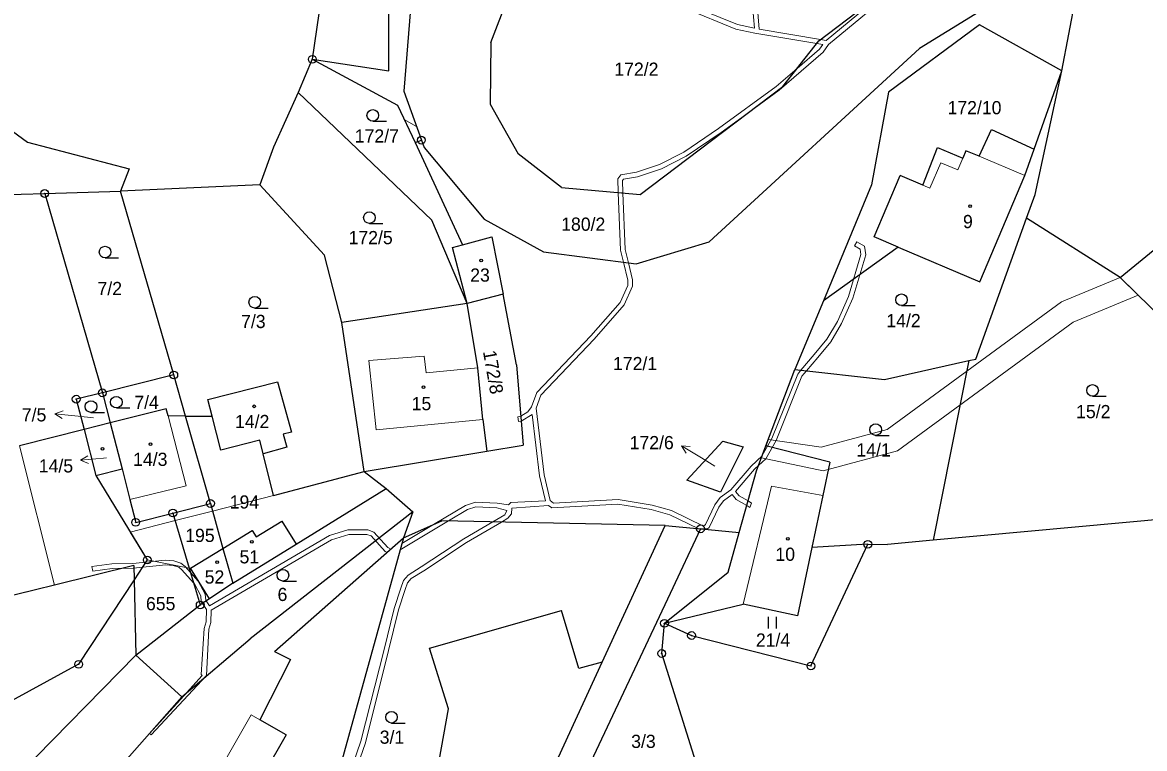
# Model space of a CAD drawing. Extents: x -653193 to -651624, y -1092017 to -1090260.
# Drawn here: x -652971.4 to -652826.7, y -1091343.3 to -1091249.7 of the extents above; entities that cross this region are included whole.
import ezdxf
from ezdxf.enums import TextEntityAlignment as Align

# ---------------------------------------------------------------- set-up
doc = ezdxf.new("R2010")
doc.units = 0
doc.header["$LTSCALE"] = 0.68
for name, color, linetype, lineweight in [('1', 7, 'Continuous', 25), ('13', 7, 'Continuous', 13), ('3', 7, 'Continuous', 25), ('4', 7, 'Continuous', 13), ('5', 7, 'Continuous', 25), ('7', 7, 'Continuous', 13), ('8', 7, 'Continuous', 25)]:
    doc.layers.add(name, color=color, linetype=linetype, lineweight=lineweight)
doc.layers.add('2', color=7, linetype='Continuous')

msp = doc.modelspace()

# ---------------------------------------------------------------- linework, layer by layer
at = {"layer": '1'}
for p, q in [((-652868.72, -1091252.07), (-652827.4, -1091220.4)), ((-652931.22, -1091234.98), (-652934.04, -1091254.46)), ((-652924.16, -1091255.94), (-652924.17, -1091237.24)), ((-652834.31, -1091239.8), (-652855.74, -1091253.08)), ((-652837.4, -1091255.94), (-652834.31, -1091239.8)), ((-652911.02, -1091252.3), (-652906.87, -1091241.53)), ((-652921.38, -1091247.95), (-652922.24, -1091258.57)), ((-652848.02, -1091250), (-652859.77, -1091258.7)), ((-652837.4, -1091255.94), (-652848.02, -1091250)), ((-652911.02, -1091252.3), (-652911.1, -1091260.26)), ((-652873.4, -1091257.98), (-652868.72, -1091252.07)), ((-652882.87, -1091278.01), (-652855.74, -1091253.08)), ((-652934.04, -1091254.46), (-652935.88, -1091258.76)), ((-652934.04, -1091254.46), (-652924.16, -1091255.94)), ((-652934.04, -1091254.46), (-652923.04, -1091260.36)), ((-652840.98, -1091266.06), (-652837.4, -1091255.94)), ((-652840.87, -1091271.87), (-652837.4, -1091255.94)), ((-652980.24, -1091258.22), (-652970.74, -1091265.15)), ((-652891.79, -1091271.87), (-652873.4, -1091257.98)), ((-652935.88, -1091258.76), (-652939.03, -1091265.77)), ((-652935.88, -1091258.76), (-652918.63, -1091275.21)), ((-652922.24, -1091258.57), (-652919.98, -1091264.88)), ((-652859.77, -1091258.7), (-652861.96, -1091270.63)), ((-652923.04, -1091260.36), (-652920.79, -1091265.2)), ((-652911.1, -1091260.26), (-652907.48, -1091266.64)), ((-652848.08, -1091266.96), (-652846.48, -1091263.49)), ((-652846.48, -1091263.49), (-652840.98, -1091266.06)), ((-652970.74, -1091265.15), (-652957.64, -1091268.57)), ((-652920.79, -1091265.2), (-652919.98, -1091264.88)), ((-652920.79, -1091265.2), (-652914.69, -1091278.37)), ((-652919.98, -1091264.88), (-652919.64, -1091265.84)), ((-652939.03, -1091265.77), (-652940.82, -1091270.66)), ((-652919.64, -1091265.84), (-652911.87, -1091275.05)), ((-652901.92, -1091270.97), (-652907.48, -1091266.64)), ((-652855.35, -1091270.69), (-652853.45, -1091265.85)), ((-652853.45, -1091265.85), (-652850.19, -1091267.2)), ((-652849.78, -1091266.24), (-652850.19, -1091267.2)), ((-652848.08, -1091266.96), (-652849.78, -1091266.24)), ((-652842.19, -1091269.46), (-652840.98, -1091266.06)), ((-652957.64, -1091268.57), (-652958.79, -1091271.46)), ((-652861.6, -1091277.36), (-652858.26, -1091269.45)), ((-652855.35, -1091270.69), (-652858.26, -1091269.45)), ((-652847.98, -1091283.13), (-652842.19, -1091269.46)), ((-652940.82, -1091270.66), (-652958.79, -1091271.46)), ((-652940.82, -1091270.66), (-652932.49, -1091279.7)), ((-652901.92, -1091270.97), (-652891.79, -1091271.87)), ((-652861.96, -1091270.63), (-652868.15, -1091285.58)), ((-652975.2, -1091271.97), (-652968.54, -1091271.76)), ((-652968.54, -1091271.76), (-652958.79, -1091271.46)), ((-652968.54, -1091271.76), (-652961.1, -1091297.46)), ((-652951.9, -1091295.15), (-652958.79, -1091271.46)), ((-652841.98, -1091274.95), (-652840.87, -1091271.87)), ((-652914.09, -1091285.93), (-652918.63, -1091275.21)), ((-652911.87, -1091275.05), (-652904.23, -1091279.27)), ((-652848.49, -1091293.1), (-652841.98, -1091274.95)), ((-652829.87, -1091282.59), (-652841.98, -1091274.95)), ((-652915.97, -1091278.71), (-652914.69, -1091278.37)), ((-652914.69, -1091278.37), (-652910.9, -1091277.36)), ((-652910.9, -1091277.36), (-652909.43, -1091284.72)), ((-652892.28, -1091280.84), (-652882.87, -1091278.01)), ((-652858.49, -1091278.67), (-652861.6, -1091277.36)), ((-652930.22, -1091288.41), (-652932.49, -1091279.7)), ((-652914.09, -1091285.93), (-652915.97, -1091278.71)), ((-652904.23, -1091279.27), (-652892.28, -1091280.84)), ((-652858.49, -1091278.67), (-652868.15, -1091285.58)), ((-652858.49, -1091278.67), (-652847.98, -1091283.13)), ((-652909.43, -1091284.72), (-652914.09, -1091285.93)), ((-652907.72, -1091293.86), (-652909.43, -1091284.72)), ((-652868.15, -1091285.58), (-652871.82, -1091294.46)), ((-652914.09, -1091285.93), (-652930.22, -1091288.41)), ((-652912.71, -1091294.23), (-652914.09, -1091285.93)), ((-652927.34, -1091307.6), (-652930.22, -1091288.41)), ((-652912.05, -1091300.89), (-652912.71, -1091294.23)), ((-652907.72, -1091293.86), (-652906.85, -1091304.2)), ((-652875.56, -1091304.31), (-652871.82, -1091294.46)), ((-652871.82, -1091294.46), (-652860.27, -1091295.72)), ((-652860.27, -1091295.72), (-652849.42, -1091293.31)), ((-652849.42, -1091293.31), (-652854.02, -1091316.45)), ((-652849.42, -1091293.31), (-652848.49, -1091293.1)), ((-652951.9, -1091295.15), (-652961.1, -1091297.46)), ((-652950.37, -1091300.46), (-652951.9, -1091295.15)), ((-652947.52, -1091298.33), (-652938.51, -1091296.02)), ((-652938.51, -1091296.02), (-652936.72, -1091302.52)), ((-652961.1, -1091297.46), (-652964.48, -1091298.27)), ((-652964.48, -1091298.27), (-652963.46, -1091302.17)), ((-652961.1, -1091297.46), (-652960.11, -1091301.32)), ((-652946.95, -1091300.48), (-652947.52, -1091298.33)), ((-652952.87, -1091299.53), (-652960.11, -1091301.32)), ((-652952.64, -1091300.44), (-652952.87, -1091299.53)), ((-652960.11, -1091301.32), (-652963.46, -1091302.17)), ((-652960.11, -1091301.32), (-652958.57, -1091307.24)), ((-652950.37, -1091300.46), (-652952.64, -1091300.44)), ((-652950.37, -1091300.46), (-652946.95, -1091300.48)), ((-652947.17, -1091311.72), (-652950.37, -1091300.46)), ((-652945.83, -1091304.83), (-652946.95, -1091300.48)), ((-652912.05, -1091300.89), (-652911.54, -1091304.98)), ((-652963.46, -1091302.17), (-652971.81, -1091304.28)), ((-652963.46, -1091302.17), (-652961.97, -1091308.11)), ((-652936.72, -1091302.52), (-652937.79, -1091302.78)), ((-652937.79, -1091302.78), (-652937.32, -1091304.47)), ((-652940.81, -1091303.56), (-652945.83, -1091304.83)), ((-652940.38, -1091305.3), (-652940.81, -1091303.56)), ((-652937.32, -1091304.47), (-652940.38, -1091305.3)), ((-652911.54, -1091304.98), (-652906.85, -1091304.2)), ((-652885.76, -1091308.73), (-652881.13, -1091303.69)), ((-652878.5, -1091304.43), (-652881.43, -1091310.26)), ((-652881.13, -1091303.69), (-652878.5, -1091304.43)), ((-652876.78, -1091307.52), (-652875.56, -1091304.31)), ((-652867.31, -1091306.39), (-652875.56, -1091304.31)), ((-652939.05, -1091310.69), (-652940.38, -1091305.3)), ((-652927.34, -1091307.6), (-652911.54, -1091304.98)), ((-652961.97, -1091308.11), (-652958.57, -1091307.24)), ((-652958.57, -1091307.24), (-652957.56, -1091311.21)), ((-652879, -1091315.45), (-652876.78, -1091307.52)), ((-652867.31, -1091306.39), (-652868.21, -1091310.68)), ((-652961.97, -1091308.11), (-652955.32, -1091319)), ((-652939.05, -1091310.69), (-652927.34, -1091307.6)), ((-652927.34, -1091307.6), (-652924.54, -1091309.8)), ((-652881.43, -1091310.26), (-652885.76, -1091308.73)), ((-652936.13, -1091316.95), (-652924.54, -1091309.8)), ((-652924.54, -1091309.8), (-652921.09, -1091312.8)), ((-652957.56, -1091311.21), (-652956.81, -1091314.16)), ((-652952.02, -1091312.95), (-652947.17, -1091311.72)), ((-652947.17, -1091311.72), (-652945.56, -1091317.51)), ((-652800.34, -1091311.51), (-652854.02, -1091316.45)), ((-652956.81, -1091314.16), (-652952.02, -1091312.95)), ((-652952.02, -1091312.95), (-652949.91, -1091320.04)), ((-652921.09, -1091312.8), (-652942.07, -1091329.19)), ((-652921.09, -1091312.8), (-652922.28, -1091316.16)), ((-652941.28, -1091316.03), (-652937.97, -1091314)), ((-652937.97, -1091314), (-652936.13, -1091316.95)), ((-652922.28, -1091316.16), (-652917.35, -1091313.95)), ((-652888.57, -1091314.54), (-652917.35, -1091313.95)), ((-652896.68, -1091332.18), (-652888.57, -1091314.54)), ((-652888.57, -1091314.54), (-652883.99, -1091314.99)), ((-652945.56, -1091317.51), (-652941.81, -1091315.21)), ((-652941.81, -1091315.21), (-652941.28, -1091316.03)), ((-652938.9, -1091330.8), (-652922.28, -1091316.16)), ((-652922.28, -1091316.16), (-652931.8, -1091350.57)), ((-652883.99, -1091314.99), (-652887.91, -1091323.32)), ((-652883.99, -1091314.99), (-652882.99, -1091315.06)), ((-652882.99, -1091315.06), (-652879, -1091315.45)), ((-652880.44, -1091320.59), (-652879, -1091315.45)), ((-652949.74, -1091320.07), (-652945.56, -1091317.51)), ((-652945.56, -1091317.51), (-652944.3, -1091321.99)), ((-652944.3, -1091321.99), (-652936.13, -1091316.95)), ((-652869.76, -1091332.67), (-652862.42, -1091316.98)), ((-652862.42, -1091316.98), (-652869.63, -1091317.4)), ((-652862.42, -1091316.98), (-652859.89, -1091316.99)), ((-652854.02, -1091316.45), (-652859.89, -1091316.99)), ((-652955.32, -1091319), (-652957, -1091321.56)), ((-652957.04, -1091319.7), (-652967.29, -1091322.23)), ((-652957.04, -1091319.7), (-652957, -1091321.56)), ((-652949.91, -1091320.04), (-652948.49, -1091324.8)), ((-652947.29, -1091324), (-652949.74, -1091320.07)), ((-652957, -1091321.56), (-652964.17, -1091332.45)), ((-652957, -1091321.56), (-652956.81, -1091331.27)), ((-652944.3, -1091321.99), (-652947.29, -1091324)), ((-652888.64, -1091327.17), (-652880.44, -1091320.59)), ((-652967.29, -1091322.23), (-652976.34, -1091324.46)), ((-652887.91, -1091323.32), (-652903.57, -1091356.54)), ((-652956.81, -1091331.27), (-652948.49, -1091324.8)), ((-652947.29, -1091324), (-652948.49, -1091324.8)), ((-652888.64, -1091327.17), (-652878.5, -1091324.71)), ((-652871.49, -1091326.22), (-652878.5, -1091324.71)), ((-652918.95, -1091330.37), (-652901.9, -1091325.5)), ((-652899.69, -1091333), (-652901.9, -1091325.5)), ((-652888.99, -1091331.06), (-652888.64, -1091327.17)), ((-652950.87, -1091336.63), (-652942.07, -1091329.19)), ((-652916.48, -1091338.19), (-652918.95, -1091330.37)), ((-652956.81, -1091331.27), (-652971.83, -1091346.61)), ((-652950.87, -1091336.63), (-652956.81, -1091331.27)), ((-652936.87, -1091331.83), (-652940.81, -1091339.6)), ((-652938.9, -1091330.8), (-652936.87, -1091331.83)), ((-652884.37, -1091345.73), (-652888.99, -1091331.06)), ((-652964.17, -1091332.45), (-652980.42, -1091341.26)), ((-652907.57, -1091355.84), (-652896.68, -1091332.18)), ((-652896.68, -1091332.18), (-652899.69, -1091333)), ((-652919.74, -1091356.26), (-652916.48, -1091338.19)), ((-652937.42, -1091341.55), (-652940.81, -1091339.6)), ((-652937.42, -1091341.55), (-652942.81, -1091350.95))]:
    msp.add_line(p, q, dxfattribs=at)
for points in [[(-652800.34, -1091311.51), (-652829.87, -1091282.59), (-652807.65, -1091264.38)], [(-652868.21, -1091310.68), (-652869.63, -1091317.4), (-652871.49, -1091326.22)], [(-652888.64, -1091327.17), (-652885.15, -1091328.74), (-652869.76, -1091332.67)]]:
    msp.add_lwpolyline(points, dxfattribs=at)
at = {"layer": '13'}
for points in [[(-652858.9, -1091244.63), (-652867.79, -1091252.03), (-652868.51, -1091251.91), (-652868.72, -1091252.07), (-652869.01, -1091252.44), (-652868.23, -1091252.57), (-652868.64, -1091253.14), (-652871.55, -1091255.65), (-652873.4, -1091257.98), (-652877.74, -1091261.26), (-652873.86, -1091258.44), (-652868.2, -1091253.54), (-652867.48, -1091252.56), (-652858.42, -1091245.02)], [(-652885.94, -1091247.91), (-652879.42, -1091250.56), (-652876.98, -1091251.08), (-652869.01, -1091252.44), (-652868.72, -1091252.07), (-652868.51, -1091251.91), (-652876.42, -1091250.57), (-652876.69, -1091247.4)], [(-652877.29, -1091247.54), (-652877.04, -1091250.46), (-652879.24, -1091249.98), (-652885.7, -1091247.37)], [(-652930.22, -1091351.36), (-652927.2, -1091342.56), (-652924.21, -1091330.69), (-652922.91, -1091325.41), (-652922.07, -1091322.82), (-652921.76, -1091321.96), (-652921.29, -1091321.41), (-652919.68, -1091320.39), (-652914.17, -1091316.76), (-652909.64, -1091314.11), (-652910.78, -1091314.08), (-652914.49, -1091316.26), (-652920, -1091319.89), (-652921.69, -1091320.95), (-652922.28, -1091321.66), (-652922.63, -1091322.62), (-652923.49, -1091325.25), (-652924.79, -1091330.55), (-652927.78, -1091342.38), (-652930.82, -1091351.26)]]:
    msp.add_lwpolyline(points, dxfattribs=at)
for points in [[(-652877.74, -1091261.26), (-652873.4, -1091257.98), (-652871.55, -1091255.65), (-652874.24, -1091257.96), (-652881.69, -1091263.38), (-652886.16, -1091266.42), (-652889.28, -1091268.04), (-652892.24, -1091269.02), (-652894.28, -1091269.37), (-652894.66, -1091269.87), (-652894.59, -1091271.62), (-652893.99, -1091271.67), (-652894.06, -1091270.07), (-652893.94, -1091269.93), (-652892.1, -1091269.6), (-652889.04, -1091268.6), (-652885.86, -1091266.94), (-652881.35, -1091263.88)], [(-652920.79, -1091265.2), (-652919.98, -1091264.88), (-652920.61, -1091263.13), (-652922.18, -1091262.21)], [(-652894.59, -1091271.62), (-652894.29, -1091279.05), (-652893.92, -1091280.62), (-652893.28, -1091280.71), (-652893.69, -1091278.97), (-652893.99, -1091271.67)], [(-652864.37, -1091285.24), (-652862.69, -1091279.68), (-652862.84, -1091278.55), (-652863.83, -1091277.99), (-652864.13, -1091278.51), (-652863.4, -1091278.93), (-652863.31, -1091279.64), (-652864.93, -1091285.04), (-652866.35, -1091288.25), (-652867.69, -1091290.55), (-652869.32, -1091292.53), (-652871.04, -1091294.54), (-652870.32, -1091294.62), (-652868.86, -1091292.91), (-652867.19, -1091290.89), (-652865.81, -1091288.53)], [(-652892.77, -1091283.72), (-652892.77, -1091282.87), (-652893.28, -1091280.71), (-652893.92, -1091280.62), (-652893.37, -1091282.93), (-652893.37, -1091283.6), (-652894.36, -1091285.81), (-652898.14, -1091290.12), (-652905.1, -1091297.42), (-652905.77, -1091299.25), (-652906.27, -1091299.9), (-652907.16, -1091300.47), (-652907.12, -1091301.1), (-652905.7, -1091300.26), (-652904.76, -1091308.14), (-652903.96, -1091311.4), (-652908.46, -1091311.61), (-652908.75, -1091311.89), (-652910.21, -1091311.68), (-652913.02, -1091311.54), (-652914.3, -1091311.96), (-652918.4, -1091314.42), (-652917.35, -1091313.95), (-652916.48, -1091313.97), (-652914.04, -1091312.5), (-652912.94, -1091312.14), (-652910.27, -1091312.28), (-652908.96, -1091312.61), (-652909.22, -1091313.17), (-652910.78, -1091314.08), (-652909.64, -1091314.11), (-652908.82, -1091313.63), (-652908.37, -1091313.04), (-652908.3, -1091312.33), (-652903.58, -1091311.98), (-652903.16, -1091312.28), (-652894.67, -1091311.81), (-652890.36, -1091312.51), (-652887.95, -1091313.18), (-652884.29, -1091314.96), (-652883.99, -1091314.99), (-652883.1, -1091314.99), (-652882.88, -1091314.8), (-652881.61, -1091312.2), (-652881.04, -1091311.36), (-652879.92, -1091310.57), (-652879.4, -1091311.19), (-652878.03, -1091312), (-652877.87, -1091311.4), (-652879, -1091310.73), (-652879.48, -1091310.17), (-652877.04, -1091307.31), (-652876.52, -1091306.83), (-652876.03, -1091305.54), (-652876.05, -1091305.58), (-652877.48, -1091306.89), (-652880.07, -1091309.95), (-652881.48, -1091310.94), (-652882.13, -1091311.9), (-652883.36, -1091314.42), (-652883.6, -1091314.63), (-652887.73, -1091312.62), (-652890.24, -1091311.93), (-652894.63, -1091311.21), (-652902.96, -1091311.66), (-652903.36, -1091311.33), (-652904.16, -1091308.04), (-652905.19, -1091299.44), (-652904.58, -1091297.74), (-652897.7, -1091290.52), (-652893.84, -1091286.13)], [(-652835.96, -1091288.35), (-652827.56, -1091284.86), (-652829.87, -1091282.59), (-652837.45, -1091285.72), (-652859.92, -1091302.2), (-652868.42, -1091304.47), (-652875.24, -1091303.47), (-652876.14, -1091305.84), (-652868.2, -1091307.52), (-652858.6, -1091304.95)], [(-652870.91, -1091295.31), (-652870.32, -1091294.62), (-652871.04, -1091294.54), (-652871.46, -1091295.03), (-652874.8, -1091303.35), (-652876.03, -1091305.54), (-652876.52, -1091306.83), (-652875.57, -1091305.96), (-652874.26, -1091303.61)], [(-652907.12, -1091301.1), (-652907.16, -1091300.47), (-652907.18, -1091300.48), (-652907.53, -1091300.53), (-652907.47, -1091301.15)], [(-652957.51, -1091315.41), (-652955.32, -1091319), (-652949.91, -1091320.04), (-652949.74, -1091320.07), (-652945.56, -1091317.51), (-652941.81, -1091315.21), (-652941.28, -1091316.03), (-652937.97, -1091314), (-652936.13, -1091316.95), (-652924.54, -1091309.8), (-652927.34, -1091307.6), (-652939.05, -1091310.69), (-652946.9, -1091312.7), (-652951.73, -1091313.93)], [(-652877.65, -1091312.23), (-652877.41, -1091311.67), (-652877.87, -1091311.4), (-652878.03, -1091312)], [(-652917.35, -1091313.95), (-652918.4, -1091314.42), (-652922.48, -1091316.87), (-652922.71, -1091317.71), (-652916.48, -1091313.97)], [(-652947.1, -1091325.48), (-652931.58, -1091316.39), (-652929.34, -1091315.73), (-652926.99, -1091315.7), (-652926.46, -1091315.91), (-652924.66, -1091317.91), (-652924.4, -1091318.03), (-652923.91, -1091317.59), (-652924.3, -1091317.41), (-652926.1, -1091315.41), (-652926.87, -1091315.1), (-652929.44, -1091315.13), (-652931.82, -1091315.83), (-652947.29, -1091324.9), (-652947.71, -1091324.28), (-652948.2, -1091324.61), (-652947.69, -1091325.39), (-652947.74, -1091326.96), (-652947.99, -1091327.84), (-652948.38, -1091333.77), (-652948.22, -1091333.91), (-652951.02, -1091336.97), (-652955.04, -1091341.36), (-652954.83, -1091341.56), (-652947.7, -1091333.91), (-652947.39, -1091327.94), (-652947.14, -1091327.06)], [(-652952.91, -1091319.62), (-652952, -1091319.72), (-652951.25, -1091319.94), (-652950.85, -1091320.27), (-652949.34, -1091321.95), (-652949.74, -1091320.6), (-652950.43, -1091319.83), (-652950.97, -1091319.4), (-652951.88, -1091319.12), (-652953, -1091319.01), (-652957.17, -1091319.47), (-652959.87, -1091319.49), (-652962.47, -1091319.85), (-652962.32, -1091320.44), (-652959.83, -1091320.09), (-652957.15, -1091320.07)], [(-652948.74, -1091321.72), (-652949.74, -1091320.6), (-652949.34, -1091321.95), (-652949.24, -1091322.06), (-652948.42, -1091323.61), (-652948.36, -1091324.37), (-652948.2, -1091324.61), (-652947.71, -1091324.28), (-652947.78, -1091324.17), (-652947.84, -1091323.43)]]:
    msp.add_lwpolyline(points, close=True, dxfattribs=at)
at = {"layer": '3'}
for p, q in [((-652926.243, -1091262.44), (-652924.493, -1091262.44)), ((-652926.683, -1091275.62), (-652924.933, -1091275.62)), ((-652960.763, -1091280.06), (-652959.013, -1091280.06)), ((-652941.463, -1091286.53), (-652939.713, -1091286.53)), ((-652858.083, -1091286.21), (-652856.333, -1091286.21)), ((-652833.453, -1091297.89), (-652831.703, -1091297.89)), ((-652962.573, -1091299.98), (-652960.823, -1091299.98)), ((-652959.303, -1091299.41), (-652957.553, -1091299.41)), ((-652861.413, -1091302.95), (-652859.663, -1091302.95)), ((-652937.823, -1091321.72), (-652936.073, -1091321.72)), ((-652875.211, -1091327.85), (-652875.211, -1091326.35)), ((-652874.21, -1091327.85), (-652874.21, -1091326.35)), ((-652923.833, -1091340.02), (-652922.083, -1091340.02))]:
    msp.add_line(p, q, dxfattribs=at)
for centre in [(-652926.2429, -1091261.6898), (-652926.6829, -1091274.8698), (-652960.7629, -1091279.3098), (-652941.4629, -1091285.7798), (-652858.0829, -1091285.4598), (-652833.4529, -1091297.1398), (-652962.5729, -1091299.2298), (-652959.3029, -1091298.6598), (-652861.4129, -1091302.1998), (-652937.8229, -1091320.9698), (-652923.8329, -1091339.2698)]:
    msp.add_circle(centre, 0.75, dxfattribs=at)
at = {"layer": '4'}
for p, q in [((-652842.19, -1091269.46), (-652848.08, -1091266.96)), ((-652850.19, -1091267.2), (-652850.84, -1091268.73)), ((-652854.42, -1091271.08), (-652855.35, -1091270.69)), ((-652926.75, -1091293.3), (-652919.6, -1091292.71)), ((-652919.6, -1091292.71), (-652919.38, -1091294.86)), ((-652925.81, -1091302.22), (-652926.75, -1091293.3)), ((-652912.71, -1091294.23), (-652919.38, -1091294.86)), ((-652950.31, -1091309.44), (-652952.64, -1091300.44)), ((-652925.81, -1091302.22), (-652912.05, -1091300.89)), ((-652971.81, -1091304.28), (-652967.29, -1091322.23)), ((-652950.31, -1091309.44), (-652957.56, -1091311.21)), ((-652874.84, -1091309.51), (-652878.5, -1091324.71)), ((-652868.21, -1091310.68), (-652874.84, -1091309.51)), ((-652964.2, -1091351.74), (-652950.87, -1091336.63)), ((-652947.29, -1091348.34), (-652941.92, -1091338.96)), ((-652940.81, -1091339.6), (-652941.92, -1091338.96))]:
    msp.add_line(p, q, dxfattribs=at)
msp.add_lwpolyline([(-652850.84, -1091268.73), (-652853.03, -1091267.8), (-652854.42, -1091271.08)], dxfattribs=at)
at = {"layer": '5'}
for centre in [(-652849.2468, -1091273.4092), (-652912.2568, -1091280.4092), (-652919.6968, -1091296.7392), (-652941.5268, -1091299.1992), (-652961.0868, -1091304.6692), (-652954.8968, -1091304.0892), (-652872.7468, -1091316.2692), (-652941.8468, -1091316.6792), (-652946.3068, -1091319.2892)]:
    msp.add_circle(centre, 0.175, dxfattribs=at)
at = {"layer": '7'}
for p, q in [((-652967.215, -1091300.166), (-652966.271, -1091300.769)), ((-652886.442, -1091304.304), (-652885.842, -1091305.249)), ((-652963.93, -1091306.152), (-652962.888, -1091306.563))]:
    msp.add_line(p, q, dxfattribs=at)
for points in [[(-652962.23, -1091300.69), (-652964.23, -1091300.48), (-652967.215, -1091300.166), (-652966.166, -1091299.773)], [(-652882.16, -1091306.89), (-652883.87, -1091305.85), (-652886.442, -1091304.304), (-652885.326, -1091304.391)], [(-652960.57, -1091305.85), (-652960.94, -1091305.89), (-652963.93, -1091306.152), (-652962.976, -1091305.565)]]:
    msp.add_lwpolyline(points, dxfattribs=at)
at = {"layer": '8'}
for centre, radius in [((-652934.04, -1091254.4599), 0.5), ((-652934.04, -1091254.4599), 0.0303), ((-652919.98, -1091264.8799), 0.5), ((-652919.98, -1091264.8799), 0.0303), ((-652968.54, -1091271.7599), 0.5), ((-652968.54, -1091271.7599), 0.0303), ((-652951.9, -1091295.1499), 0.5), ((-652951.9, -1091295.1499), 0.0303), ((-652961.1, -1091297.4599), 0.5), ((-652964.48, -1091298.2699), 0.5), ((-652964.48, -1091298.2699), 0.0303), ((-652961.1, -1091297.4599), 0.0303), ((-652947.17, -1091311.7199), 0.5), ((-652947.17, -1091311.7199), 0.0303), ((-652952.02, -1091312.9499), 0.5), ((-652952.02, -1091312.9499), 0.0303), ((-652956.81, -1091314.1599), 0.5), ((-652956.81, -1091314.1599), 0.0303), ((-652883.99, -1091314.9899), 0.5), ((-652883.99, -1091314.9899), 0.0303), ((-652862.42, -1091316.9799), 0.5), ((-652862.42, -1091316.9799), 0.0303), ((-652955.32, -1091318.9999), 0.5), ((-652955.32, -1091318.9999), 0.0303), ((-652948.49, -1091324.7999), 0.5), ((-652948.49, -1091324.7999), 0.0303), ((-652888.64, -1091327.1699), 0.5), ((-652888.64, -1091327.1699), 0.0303), ((-652885.15, -1091328.7399), 0.5), ((-652885.15, -1091328.7399), 0.0303), ((-652888.99, -1091331.0599), 0.5), ((-652964.17, -1091332.4499), 0.5), ((-652888.99, -1091331.0599), 0.0303), ((-652964.17, -1091332.4499), 0.0303), ((-652869.76, -1091332.6699), 0.5), ((-652869.76, -1091332.6699), 0.0303)]:
    msp.add_circle(centre, radius, dxfattribs=at)

# ---------------------------------------------------------------- texts
at = {"layer": '2'}
for s, p in [('172/2', (-652892.26, -1091256.585)), ('172/10', (-652848.67, -1091261.545)), ('172/7', (-652925.72, -1091265.195)), ('180/2', (-652899.11, -1091276.565)), ('9', (-652849.52, -1091276.225)), ('172/5', (-652926.52, -1091278.295)), ('23', (-652912.419, -1091283.125)), ('7/2', (-652960.15, -1091284.855)), ('14/2', (-652857.819, -1091288.995)), ('7/3', (-652941.64, -1091289.105)), ('172/1', (-652892.43, -1091294.535)), ('7/4', (-652955.41, -1091299.535)), ('15', (-652919.969, -1091299.695)), ('7/5', (-652969.91, -1091301.145)), ('14/2', (-652941.789, -1091302.005)), ('15/2', (-652833.359, -1091300.725)), ('14/1', (-652861.679, -1091305.665)), ('14/5', (-652967.089, -1091307.725)), ('14/3', (-652954.929, -1091306.875)), ('194', (-652942.789, -1091312.375)), ('195', (-652948.529, -1091316.685)), ('10', (-652873.069, -1091319.115)), ('51', (-652942.159, -1091319.445)), ('52', (-652946.649, -1091322.045)), ('6', (-652937.89, -1091324.295)), ('655', (-652953.589, -1091325.485)), ('21/4', (-652874.639, -1091330.175)), ('3/1', (-652923.77, -1091342.695)), ('3/3', (-652891.35, -1091343.235))]:
    msp.add_text(s, height=1.7, dxfattribs=at).set_placement(p, align=Align.CENTER)
msp.add_text('172/8', height=1.7, rotation=280, dxfattribs=at).set_placement((-652911.5552, -1091294.9384), align=Align.CENTER)
msp.add_text('172/6', height=1.7, dxfattribs=at).set_placement((-652887.44, -1091304.725), align=Align.RIGHT)

doc.saveas('drawing.dxf')
